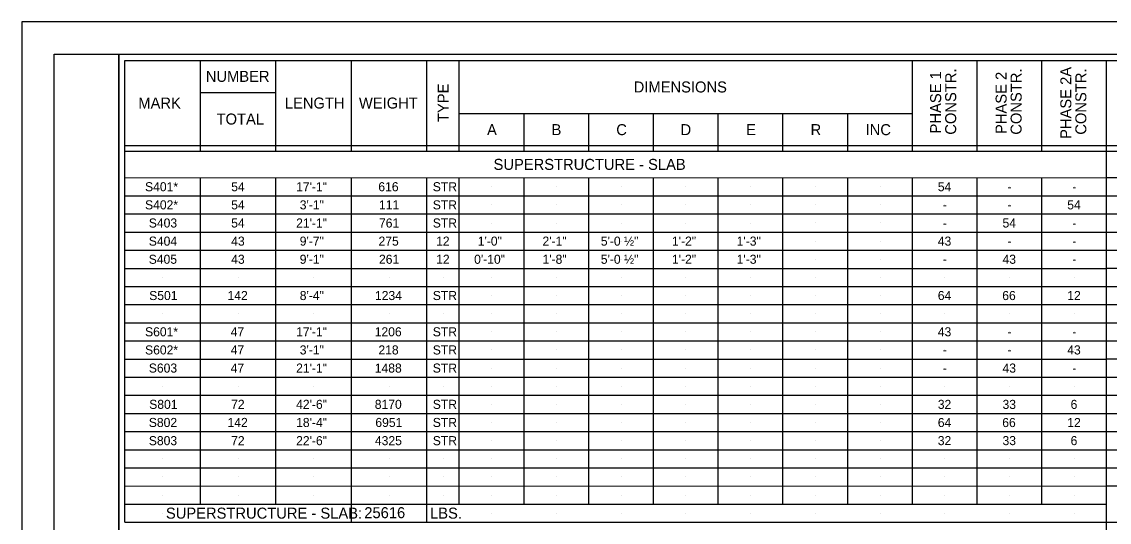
# Model space of a CAD drawing. Extents: x 0 to 34, y 0 to 22.
# Drawn here: x 0 to 16.8, y 14.27 to 22 of the extents above; entities that cross this region are included whole.
import ezdxf

# ---------------------------------------------------------------- set-up
doc = ezdxf.new("R2010")
doc.units = 0
for name, color, linetype in [('BR_P_Gen_Text', 7, 'Continuous'), ('Default', 7, 'Continuous'), ('SH_Border', 7, 'Continuous'), ('SH_Cut_Line', 7, 'Continuous')]:
    doc.layers.add(name, color=color, linetype=linetype)

msp = doc.modelspace()

# ---------------------------------------------------------------- linework, layer by layer
at = {"layer": 'BR_P_Gen_Text'}
for p, q in [((1.593, 14.272), (1.593, 21.404)), ((1.593, 21.404), (16.76, 21.404)), ((2.76, 20.004), (2.76, 21.404)), ((3.927, 20.004), (3.927, 21.404)), ((5.093, 20.004), (5.093, 21.404)), ((6.26, 20.004), (6.26, 21.404)), ((6.76, 20.004), (6.76, 21.404)), ((13.76, 20.004), (13.76, 21.404)), ((14.76, 20.004), (14.76, 21.404)), ((15.76, 20.004), (15.76, 21.404)), ((16.76, 14.272), (16.76, 21.404)), ((16.76, 14.273), (16.76, 21.404)), ((16.76, 21.404), (31.927, 21.404)), ((2.774, 20.91), (3.927, 20.91)), ((6.76, 20.581), (13.76, 20.581)), ((7.76, 20.004), (7.76, 20.581)), ((8.76, 20.004), (8.76, 20.581)), ((9.76, 20.004), (9.76, 20.581)), ((10.76, 20.004), (10.76, 20.581)), ((11.76, 20.004), (11.76, 20.581)), ((12.76, 20.004), (12.76, 20.581)), ((1.593, 20.087), (16.76, 20.087)), ((1.593, 20.004), (16.76, 20.004)), ((16.76, 20.087), (31.927, 20.087)), ((16.76, 20.004), (31.927, 20.004)), ((7.677, 19.798), (7.677, 19.798)), ((1.593, 19.592), (16.76, 19.593)), ((2.76, 14.552), (2.76, 19.593)), ((3.927, 14.552), (3.927, 19.593)), ((5.093, 14.272), (5.093, 19.593)), ((6.26, 14.272), (6.26, 19.593)), ((6.76, 14.553), (6.76, 19.593)), ((7.76, 14.553), (7.76, 19.593)), ((8.76, 14.553), (8.76, 19.593)), ((9.76, 14.553), (9.76, 19.593)), ((10.76, 14.553), (10.76, 19.593)), ((11.76, 14.553), (11.76, 19.593)), ((12.76, 14.553), (12.76, 19.593)), ((13.76, 14.553), (13.76, 19.593)), ((14.76, 14.553), (14.76, 19.593)), ((15.76, 14.553), (15.76, 19.593)), ((16.76, 19.593), (31.927, 19.593)), ((2.177, 19.453), (2.177, 19.453)), ((3.343, 19.453), (3.343, 19.453)), ((4.51, 19.453), (4.51, 19.453)), ((5.677, 19.453), (5.677, 19.453)), ((6.51, 19.453), (6.51, 19.453)), ((7.26, 19.453), (7.26, 19.453)), ((8.26, 19.453), (8.26, 19.453)), ((9.26, 19.453), (9.26, 19.453)), ((10.26, 19.453), (10.26, 19.453)), ((11.26, 19.453), (11.26, 19.453)), ((12.26, 19.453), (12.26, 19.453)), ((13.26, 19.453), (13.26, 19.453)), ((14.26, 19.453), (14.26, 19.453)), ((15.26, 19.453), (15.26, 19.453)), ((16.26, 19.453), (16.26, 19.453)), ((1.593, 19.312), (16.76, 19.312)), ((2.177, 19.172), (2.177, 19.172)), ((3.343, 19.172), (3.343, 19.172)), ((4.51, 19.173), (4.51, 19.173)), ((5.677, 19.173), (5.677, 19.173)), ((6.51, 19.172), (6.51, 19.172)), ((7.26, 19.172), (7.26, 19.172)), ((8.26, 19.172), (8.26, 19.172)), ((9.26, 19.172), (9.26, 19.172)), ((10.26, 19.172), (10.26, 19.172)), ((11.26, 19.172), (11.26, 19.172)), ((12.26, 19.173), (12.26, 19.173)), ((13.26, 19.173), (13.26, 19.173)), ((14.26, 19.172), (14.26, 19.172)), ((15.26, 19.172), (15.26, 19.172)), ((16.26, 19.172), (16.26, 19.172)), ((16.76, 19.313), (31.927, 19.313)), ((1.593, 19.032), (16.76, 19.032)), ((16.76, 19.033), (31.927, 19.033)), ((2.177, 18.892), (2.177, 18.892)), ((3.343, 18.892), (3.343, 18.892)), ((4.51, 18.893), (4.51, 18.893)), ((5.677, 18.893), (5.677, 18.893)), ((6.51, 18.892), (6.51, 18.892)), ((7.26, 18.892), (7.26, 18.892)), ((8.26, 18.892), (8.26, 18.892)), ((9.26, 18.892), (9.26, 18.892)), ((10.26, 18.892), (10.26, 18.892)), ((11.26, 18.892), (11.26, 18.892)), ((12.26, 18.893), (12.26, 18.893)), ((13.26, 18.893), (13.26, 18.893)), ((14.26, 18.892), (14.26, 18.892)), ((15.26, 18.892), (15.26, 18.892)), ((16.26, 18.892), (16.26, 18.892)), ((1.593, 18.752), (16.76, 18.752)), ((16.76, 18.753), (31.927, 18.753)), ((2.177, 18.612), (2.177, 18.612)), ((2.177, 18.612), (2.177, 18.612)), ((7.26, 18.612), (7.26, 18.612)), ((8.26, 18.612), (8.26, 18.612)), ((9.26, 18.612), (9.26, 18.612)), ((10.26, 18.612), (10.26, 18.612)), ((11.26, 18.612), (11.26, 18.612)), ((12.26, 18.613), (12.26, 18.613)), ((13.26, 18.613), (13.26, 18.613)), ((14.26, 18.612), (14.26, 18.612)), ((15.26, 18.612), (15.26, 18.612)), ((16.26, 18.612), (16.26, 18.612)), ((1.593, 18.472), (16.76, 18.472)), ((2.177, 18.332), (2.177, 18.332)), ((3.343, 18.332), (3.343, 18.332)), ((4.51, 18.333), (4.51, 18.333)), ((5.677, 18.333), (5.677, 18.333)), ((6.51, 18.332), (6.51, 18.332)), ((7.26, 18.332), (7.26, 18.332)), ((8.26, 18.332), (8.26, 18.332)), ((9.26, 18.332), (9.26, 18.332)), ((10.26, 18.332), (10.26, 18.332)), ((11.26, 18.332), (11.26, 18.332)), ((12.26, 18.333), (12.26, 18.333)), ((13.26, 18.333), (13.26, 18.333)), ((14.26, 18.332), (14.26, 18.332)), ((15.26, 18.332), (15.26, 18.332)), ((16.26, 18.332), (16.26, 18.332)), ((16.76, 18.473), (31.927, 18.473)), ((1.593, 18.192), (16.76, 18.192)), ((16.76, 18.193), (31.927, 18.193)), ((2.177, 18.052), (2.177, 18.052)), ((3.343, 18.052), (3.343, 18.052)), ((4.51, 18.053), (4.51, 18.053)), ((5.677, 18.053), (5.677, 18.053)), ((6.51, 18.052), (6.51, 18.052)), ((7.26, 18.052), (7.26, 18.052)), ((8.26, 18.052), (8.26, 18.052)), ((9.26, 18.052), (9.26, 18.052)), ((10.26, 18.052), (10.26, 18.052)), ((11.26, 18.052), (11.26, 18.052)), ((12.26, 18.053), (12.26, 18.053)), ((13.26, 18.053), (13.26, 18.053)), ((14.26, 18.052), (14.26, 18.052)), ((15.26, 18.052), (15.26, 18.052)), ((16.26, 18.052), (16.26, 18.052)), ((1.593, 17.912), (16.76, 17.913)), ((16.76, 17.913), (31.927, 17.913)), ((2.177, 17.773), (2.177, 17.773)), ((3.343, 17.773), (3.343, 17.773)), ((4.51, 17.773), (4.51, 17.773)), ((5.677, 17.773), (5.677, 17.773)), ((6.51, 17.773), (6.51, 17.773)), ((7.26, 17.773), (7.26, 17.773)), ((8.26, 17.773), (8.26, 17.773)), ((9.26, 17.773), (9.26, 17.773)), ((10.26, 17.773), (10.26, 17.773)), ((11.26, 17.773), (11.26, 17.773)), ((12.26, 17.773), (12.26, 17.773)), ((13.26, 17.773), (13.26, 17.773)), ((14.26, 17.773), (14.26, 17.773)), ((15.26, 17.773), (15.26, 17.773)), ((16.26, 17.773), (16.26, 17.773)), ((1.593, 17.632), (16.76, 17.633)), ((2.177, 17.493), (2.177, 17.493)), ((2.177, 17.493), (2.177, 17.493)), ((3.343, 17.493), (3.343, 17.493)), ((3.343, 17.493), (3.343, 17.493)), ((4.51, 17.493), (4.51, 17.493)), ((4.51, 17.493), (4.51, 17.493)), ((5.677, 17.493), (5.677, 17.493)), ((5.677, 17.493), (5.677, 17.493)), ((6.51, 17.493), (6.51, 17.493)), ((6.51, 17.493), (6.51, 17.493)), ((7.26, 17.493), (7.26, 17.493)), ((7.26, 17.493), (7.26, 17.493)), ((8.26, 17.493), (8.26, 17.493)), ((8.26, 17.493), (8.26, 17.493)), ((9.26, 17.493), (9.26, 17.493)), ((9.26, 17.493), (9.26, 17.493)), ((10.26, 17.493), (10.26, 17.493)), ((10.26, 17.493), (10.26, 17.493)), ((11.26, 17.493), (11.26, 17.493)), ((11.26, 17.493), (11.26, 17.493)), ((12.26, 17.493), (12.26, 17.493)), ((12.26, 17.493), (12.26, 17.493)), ((13.26, 17.493), (13.26, 17.493)), ((13.26, 17.493), (13.26, 17.493)), ((14.26, 17.493), (14.26, 17.493)), ((15.26, 17.493), (15.26, 17.493)), ((16.26, 17.493), (16.26, 17.493)), ((16.76, 17.633), (31.927, 17.633)), ((1.593, 17.352), (16.76, 17.353)), ((16.76, 17.353), (31.927, 17.353)), ((2.177, 17.213), (2.177, 17.213)), ((2.177, 17.213), (2.177, 17.213)), ((3.343, 17.213), (3.343, 17.213)), ((3.343, 17.213), (3.343, 17.213)), ((4.51, 17.213), (4.51, 17.213)), ((4.51, 17.213), (4.51, 17.213)), ((5.677, 17.213), (5.677, 17.213)), ((5.677, 17.213), (5.677, 17.213)), ((6.51, 17.213), (6.51, 17.213)), ((6.51, 17.213), (6.51, 17.213)), ((7.26, 17.213), (7.26, 17.213)), ((7.26, 17.213), (7.26, 17.213)), ((8.26, 17.213), (8.26, 17.213)), ((8.26, 17.213), (8.26, 17.213)), ((9.26, 17.213), (9.26, 17.213)), ((9.26, 17.213), (9.26, 17.213)), ((10.26, 17.213), (10.26, 17.213)), ((10.26, 17.213), (10.26, 17.213)), ((11.26, 17.213), (11.26, 17.213)), ((11.26, 17.213), (11.26, 17.213)), ((12.26, 17.213), (12.26, 17.213)), ((12.26, 17.213), (12.26, 17.213)), ((13.26, 17.213), (13.26, 17.213)), ((13.26, 17.213), (13.26, 17.213)), ((14.26, 17.213), (14.26, 17.213)), ((14.26, 17.213), (14.26, 17.213)), ((15.26, 17.213), (15.26, 17.213)), ((15.26, 17.213), (15.26, 17.213)), ((16.26, 17.213), (16.26, 17.213)), ((16.26, 17.213), (16.26, 17.213)), ((1.593, 17.072), (16.76, 17.073)), ((16.76, 17.073), (31.927, 17.073)), ((2.177, 16.932), (2.177, 16.932)), ((3.343, 16.932), (3.343, 16.932)), ((4.51, 16.933), (4.51, 16.933)), ((5.677, 16.933), (5.677, 16.933)), ((6.51, 16.932), (6.51, 16.932)), ((7.26, 16.932), (7.26, 16.932)), ((8.26, 16.932), (8.26, 16.932)), ((9.26, 16.932), (9.26, 16.932)), ((10.26, 16.932), (10.26, 16.932)), ((11.26, 16.932), (11.26, 16.932)), ((12.26, 16.933), (12.26, 16.933)), ((13.26, 16.933), (13.26, 16.933)), ((14.26, 16.932), (14.26, 16.932)), ((15.26, 16.932), (15.26, 16.932)), ((16.26, 16.932), (16.26, 16.932)), ((1.593, 16.792), (16.76, 16.792)), ((2.177, 16.652), (2.177, 16.652)), ((3.343, 16.652), (3.343, 16.652)), ((4.51, 16.653), (4.51, 16.653)), ((5.677, 16.653), (5.677, 16.653)), ((6.51, 16.652), (6.51, 16.652)), ((7.26, 16.652), (7.26, 16.652)), ((8.26, 16.652), (8.26, 16.652)), ((9.26, 16.652), (9.26, 16.652)), ((10.26, 16.652), (10.26, 16.652)), ((11.26, 16.652), (11.26, 16.652)), ((12.26, 16.653), (12.26, 16.653)), ((13.26, 16.653), (13.26, 16.653)), ((14.26, 16.652), (14.26, 16.652)), ((15.26, 16.652), (15.26, 16.652)), ((16.26, 16.652), (16.26, 16.652)), ((16.76, 16.793), (31.927, 16.793)), ((1.593, 16.512), (16.76, 16.512)), ((16.76, 16.513), (31.927, 16.513)), ((2.177, 16.372), (2.177, 16.372)), ((3.343, 16.372), (3.343, 16.372)), ((4.51, 16.373), (4.51, 16.373)), ((5.677, 16.373), (5.677, 16.373)), ((6.51, 16.372), (6.51, 16.372)), ((7.26, 16.372), (7.26, 16.372)), ((8.26, 16.372), (8.26, 16.372)), ((9.26, 16.372), (9.26, 16.372)), ((10.26, 16.372), (10.26, 16.372)), ((11.26, 16.372), (11.26, 16.372)), ((12.26, 16.373), (12.26, 16.373)), ((13.26, 16.373), (13.26, 16.373)), ((14.26, 16.372), (14.26, 16.372)), ((15.26, 16.372), (15.26, 16.372)), ((16.26, 16.372), (16.26, 16.372)), ((1.593, 16.232), (16.76, 16.232)), ((16.76, 16.233), (31.927, 16.233)), ((2.177, 16.092), (2.177, 16.092)), ((3.343, 16.092), (3.343, 16.092)), ((4.51, 16.093), (4.51, 16.093)), ((5.677, 16.093), (5.677, 16.093)), ((6.51, 16.092), (6.51, 16.092)), ((7.26, 16.092), (7.26, 16.092)), ((8.26, 16.092), (8.26, 16.092)), ((9.26, 16.092), (9.26, 16.092)), ((10.26, 16.092), (10.26, 16.092)), ((11.26, 16.092), (11.26, 16.092)), ((12.26, 16.093), (12.26, 16.093)), ((13.26, 16.093), (13.26, 16.093)), ((14.26, 16.092), (14.26, 16.092)), ((15.26, 16.092), (15.26, 16.092)), ((16.26, 16.092), (16.26, 16.092)), ((1.593, 15.952), (16.76, 15.952)), ((2.177, 15.812), (2.177, 15.812)), ((3.343, 15.812), (3.343, 15.812)), ((4.51, 15.813), (4.51, 15.813)), ((5.677, 15.813), (5.677, 15.813)), ((6.51, 15.812), (6.51, 15.812)), ((7.26, 15.812), (7.26, 15.812)), ((8.26, 15.812), (8.26, 15.812)), ((9.26, 15.812), (9.26, 15.812)), ((10.26, 15.812), (10.26, 15.812)), ((11.26, 15.812), (11.26, 15.812)), ((12.26, 15.813), (12.26, 15.813)), ((13.26, 15.813), (13.26, 15.813)), ((14.26, 15.812), (14.26, 15.812)), ((15.26, 15.812), (15.26, 15.812)), ((16.26, 15.812), (16.26, 15.812)), ((16.76, 15.953), (31.927, 15.953)), ((1.593, 15.672), (16.76, 15.672)), ((16.76, 15.673), (31.927, 15.673)), ((2.177, 15.532), (2.177, 15.532)), ((3.343, 15.532), (3.343, 15.532)), ((4.51, 15.533), (4.51, 15.533)), ((5.677, 15.533), (5.677, 15.533)), ((6.51, 15.532), (6.51, 15.532)), ((7.26, 15.532), (7.26, 15.532)), ((8.26, 15.532), (8.26, 15.532)), ((9.26, 15.532), (9.26, 15.532)), ((10.26, 15.532), (10.26, 15.532)), ((11.26, 15.532), (11.26, 15.532)), ((12.26, 15.533), (12.26, 15.533)), ((13.26, 15.533), (13.26, 15.533)), ((14.26, 15.532), (14.26, 15.532)), ((15.26, 15.532), (15.26, 15.532)), ((16.26, 15.532), (16.26, 15.532)), ((1.593, 15.392), (16.76, 15.392)), ((16.76, 15.393), (31.927, 15.393)), ((2.177, 15.252), (2.177, 15.252)), ((3.343, 15.252), (3.343, 15.252)), ((4.51, 15.252), (4.51, 15.252)), ((5.677, 15.253), (5.677, 15.253)), ((6.51, 15.252), (6.51, 15.252)), ((7.26, 15.252), (7.26, 15.252)), ((8.26, 15.252), (8.26, 15.252)), ((9.26, 15.252), (9.26, 15.252)), ((10.26, 15.252), (10.26, 15.252)), ((11.26, 15.252), (11.26, 15.252)), ((12.26, 15.252), (12.26, 15.252)), ((13.26, 15.253), (13.26, 15.253)), ((14.26, 15.252), (14.26, 15.252)), ((15.26, 15.252), (15.26, 15.252)), ((16.26, 15.252), (16.26, 15.252)), ((1.593, 15.112), (16.76, 15.113)), ((2.177, 14.972), (2.177, 14.972)), ((3.343, 14.972), (3.343, 14.972)), ((4.51, 14.972), (4.51, 14.972)), ((5.677, 14.973), (5.677, 14.973)), ((6.51, 14.972), (6.51, 14.972)), ((7.26, 14.972), (7.26, 14.972)), ((8.26, 14.972), (8.26, 14.972)), ((9.26, 14.972), (9.26, 14.972)), ((10.26, 14.972), (10.26, 14.972)), ((11.26, 14.972), (11.26, 14.972)), ((12.26, 14.972), (12.26, 14.972)), ((13.26, 14.973), (13.26, 14.973)), ((14.26, 14.972), (14.26, 14.972)), ((15.26, 14.972), (15.26, 14.972)), ((16.26, 14.972), (16.26, 14.972)), ((16.76, 15.113), (31.927, 15.113)), ((1.593, 14.832), (16.76, 14.833)), ((16.76, 14.833), (31.927, 14.833)), ((2.177, 14.692), (2.177, 14.692)), ((2.177, 14.692), (2.177, 14.692)), ((3.343, 14.692), (3.343, 14.692)), ((3.343, 14.692), (3.343, 14.692)), ((4.51, 14.692), (4.51, 14.692)), ((4.51, 14.692), (4.51, 14.692)), ((5.677, 14.693), (5.677, 14.693)), ((5.677, 14.693), (5.677, 14.693)), ((6.51, 14.692), (6.51, 14.692)), ((6.51, 14.692), (6.51, 14.692)), ((7.26, 14.692), (7.26, 14.692)), ((7.26, 14.692), (7.26, 14.692)), ((8.26, 14.692), (8.26, 14.692)), ((8.26, 14.692), (8.26, 14.692)), ((9.26, 14.692), (9.26, 14.692)), ((9.26, 14.692), (9.26, 14.692)), ((10.26, 14.692), (10.26, 14.692)), ((10.26, 14.692), (10.26, 14.692)), ((11.26, 14.692), (11.26, 14.692)), ((11.26, 14.692), (11.26, 14.692)), ((12.26, 14.692), (12.26, 14.692)), ((12.26, 14.692), (12.26, 14.692)), ((13.26, 14.693), (13.26, 14.693)), ((13.26, 14.693), (13.26, 14.693)), ((14.26, 14.692), (14.26, 14.692)), ((15.26, 14.693), (15.26, 14.693)), ((16.26, 14.693), (16.26, 14.693)), ((1.593, 14.552), (16.76, 14.553)), ((2.177, 14.412), (2.177, 14.412)), ((2.177, 14.412), (2.177, 14.412)), ((3.343, 14.412), (3.343, 14.412)), ((3.343, 14.412), (3.343, 14.412)), ((4.51, 14.412), (4.51, 14.412)), ((4.51, 14.412), (4.51, 14.412)), ((5.677, 14.413), (5.677, 14.413)), ((5.677, 14.413), (5.677, 14.413)), ((6.51, 14.412), (6.51, 14.412)), ((6.51, 14.412), (6.51, 14.412)), ((7.26, 14.412), (7.26, 14.412)), ((8.26, 14.412), (8.26, 14.412)), ((9.26, 14.412), (9.26, 14.412)), ((10.26, 14.412), (10.26, 14.412)), ((11.26, 14.412), (11.26, 14.412)), ((12.26, 14.412), (12.26, 14.412)), ((13.26, 14.413), (13.26, 14.413)), ((14.26, 14.412), (14.26, 14.412)), ((15.26, 14.413), (15.26, 14.413)), ((16.26, 14.413), (16.26, 14.413)), ((1.593, 14.272), (16.76, 14.272)), ((16.76, 14.272), (31.927, 14.273)), ((16.76, 3.872), (16.76, 14.272))]:
    msp.add_line(p, q, dxfattribs=at)
at = {"layer": 'SH_Border'}
for points in [[(0.5, 21.5), (1.5, 21.5), (1.5, 0.5), (0.5, 0.5)], [(1.5, 21.5), (33.5, 21.5), (33.5, 0.5), (1.5, 0.5)]]:
    msp.add_lwpolyline(points, close=True, dxfattribs=at)
at = {"layer": 'SH_Cut_Line'}
msp.add_lwpolyline([(0, 0), (34, 0), (34, 22), (0, 22)], close=True, dxfattribs=at)

# ---------------------------------------------------------------- texts
at = {"layer": 'BR_P_Gen_Text'}
for s, height, p in [('NUMBER', 0.17, (2.843, 21.072)), ('DIMENSIONS', 0.17, (9.454, 20.908)), ('MARK', 0.17, (1.801, 20.66)), ('LENGTH', 0.17, (4.064, 20.66)), ('WEIGHT', 0.17, (5.209, 20.66)), ('TOTAL', 0.17, (3.01, 20.413)), ('A', 0.17, (7.188, 20.249)), ('B', 0.17, (8.185, 20.249)), ('C', 0.17, (9.185, 20.249)), ('D', 0.17, (10.178, 20.249)), ('E', 0.17, (11.192, 20.249)), ('R', 0.17, (12.187, 20.249)), ('INC', 0.17, (13.037, 20.249)), ('SUPERSTRUCTURE - SLAB', 0.17, (7.289, 19.713)), ('54', 0.14, (14.152, 19.383)), ('-', 0.14, (15.23, 19.383)), ('-', 0.14, (16.23, 19.383)), ('-', 0.14, (14.23, 19.103)), ('-', 0.14, (15.23, 19.103)), ('54', 0.14, (16.152, 19.103)), ('-', 0.14, (14.23, 18.823)), ('54', 0.14, (15.152, 18.823)), ('-', 0.14, (16.23, 18.823)), ('43', 0.14, (14.152, 18.543)), ('-', 0.14, (15.23, 18.543)), ('-', 0.14, (16.23, 18.543)), ('-', 0.14, (14.23, 18.263)), ('43', 0.14, (15.152, 18.263)), ('-', 0.14, (16.23, 18.263)), ('S501', 0.14, (1.969, 17.703)), ('142', 0.14, (3.179, 17.703)), ('8\'-4"', 0.14, (4.295, 17.703)), ('1234', 0.14, (5.457, 17.703)), ('STR', 0.14, (6.35, 17.703)), ('64', 0.14, (14.152, 17.703)), ('66', 0.14, (15.148, 17.703)), ('12', 0.14, (16.152, 17.703)), ('S601*', 0.14, (1.905, 17.143)), ('47', 0.14, (3.228, 17.143)), ('17\'-1"', 0.14, (4.239, 17.143)), ('1206', 0.14, (5.453, 17.143)), ('STR', 0.14, (6.35, 17.143)), ('43', 0.14, (14.152, 17.143)), ('-', 0.14, (15.23, 17.143)), ('-', 0.14, (16.23, 17.143)), ('S602*', 0.14, (1.905, 16.863)), ('47', 0.14, (3.228, 16.863)), ('3\'-1"', 0.14, (4.295, 16.863)), ('218', 0.14, (5.51, 16.863)), ('STR', 0.14, (6.35, 16.863)), ('43', 0.14, (16.152, 16.863)), ('-', 0.14, (14.23, 16.863)), ('-', 0.14, (15.23, 16.863)), ('S603', 0.14, (1.963, 16.583)), ('47', 0.14, (3.228, 16.583)), ('21\'-1"', 0.14, (4.239, 16.583)), ('1488', 0.14, (5.454, 16.583)), ('STR', 0.14, (6.35, 16.583)), ('-', 0.14, (14.23, 16.583)), ('43', 0.14, (15.152, 16.583)), ('-', 0.14, (16.23, 16.583)), ('S801', 0.14, (1.969, 16.023)), ('72', 0.14, (3.235, 16.023)), ('42\'-6"', 0.14, (4.239, 16.023)), ('8170', 0.14, (5.454, 16.023)), ('STR', 0.14, (6.35, 16.023)), ('32', 0.14, (14.152, 16.022)), ('33', 0.14, (15.152, 16.022)), ('6', 0.14, (16.204, 16.022)), ('S802', 0.14, (1.963, 15.743)), ('142', 0.14, (3.179, 15.743)), ('18\'-4"', 0.14, (4.239, 15.743)), ('6951', 0.14, (5.463, 15.743)), ('STR', 0.14, (6.35, 15.743)), ('64', 0.14, (14.152, 15.742)), ('66', 0.14, (15.148, 15.742)), ('12', 0.14, (16.152, 15.742)), ('S803', 0.14, (1.963, 15.462)), ('72', 0.14, (3.235, 15.462)), ('22\'-6"', 0.14, (4.239, 15.462)), ('4325', 0.14, (5.456, 15.462)), ('STR', 0.14, (6.35, 15.462)), ('32', 0.14, (14.152, 15.463)), ('33', 0.14, (15.152, 15.463)), ('6', 0.14, (16.204, 15.463)), ('SUPERSTRUCTURE - SLAB:', 0.17, (2.227, 14.328)), ('25616', 0.17, (5.292, 14.335)), ('LBS.', 0.17, (6.308, 14.328))]:
    msp.add_text(s, height=height, dxfattribs=at).set_placement(p)
for s, p in [('PHASE 1', (14.204, 20.276)), ('CONSTR.', (14.436, 20.256)), ('PHASE 2', (15.215, 20.267)), ('CONSTR.', (15.447, 20.256)), ('PHASE 2A', (16.215, 20.191)), ('CONSTR.', (16.447, 20.256)), ('TYPE', (6.595, 20.452))]:
    msp.add_text(s, height=0.17, rotation=90, dxfattribs=at).set_placement(p)
at = {"layer": 'Default'}
for s, p in [('S401*', (1.905, 19.383)), ('54', (3.236, 19.383)), ('17\'-1"', (4.239, 19.383)), ('616', (5.509, 19.383)), ('STR', (6.35, 19.383)), ('S402*', (1.905, 19.103)), ('54', (3.236, 19.103)), ('3\'-1"', (4.295, 19.103)), ('111', (5.519, 19.103)), ('STR', (6.35, 19.103)), ('S403', (1.963, 18.823)), ('54', (3.236, 18.823)), ('21\'-1"', (4.239, 18.823)), ('761', (5.519, 18.823)), ('STR', (6.35, 18.823)), ('S404', (1.963, 18.543)), ('43', (3.236, 18.543)), ('9\'-7"', (4.295, 18.543)), ('275', (5.512, 18.543)), ('12', (6.402, 18.543)), ('1\'-0"', (7.045, 18.543)), ('2\'-1"', (8.045, 18.543)), ('5\'-0 ½"', (8.946, 18.543)), ('1\'-2"', (10.045, 18.543)), ('1\'-3"', (11.045, 18.543)), ('S405', (1.962, 18.263)), ('43', (3.236, 18.263)), ('9\'-1"', (4.295, 18.263)), ('261', (5.519, 18.263)), ('12', (6.402, 18.263)), ('0\'-10"', (6.989, 18.263)), ('1\'-8"', (8.045, 18.263)), ('5\'-0 ½"', (8.946, 18.263)), ('1\'-2"', (10.045, 18.263)), ('1\'-3"', (11.045, 18.263))]:
    msp.add_text(s, height=0.14, dxfattribs=at).set_placement(p)

doc.saveas('drawing.dxf')
